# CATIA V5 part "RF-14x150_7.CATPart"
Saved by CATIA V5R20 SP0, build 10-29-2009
Part number: _RF-14x150
Definition: NONE
Nomenclature: _RF-14x150
Source: Unknown
Description: PART-_RF-14x150-DESC
Bounding box of the stored display mesh (mm): x -150 to 24.5, y -7.9 to 7.9, z -7.9 to 7.9
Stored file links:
  C:\Users\Utente\Desktop\IO LAVORO\3D X SITO CF\X SITO\PLASTICA\RF\RF-14x150_7.CATPart
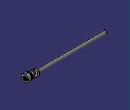
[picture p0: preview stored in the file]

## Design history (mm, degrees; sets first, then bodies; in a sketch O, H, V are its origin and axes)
Body1 "_RF-14x150" (main body)
  Solid1: solid without history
